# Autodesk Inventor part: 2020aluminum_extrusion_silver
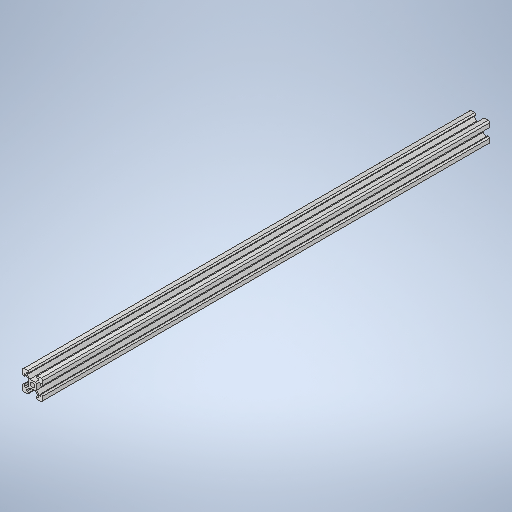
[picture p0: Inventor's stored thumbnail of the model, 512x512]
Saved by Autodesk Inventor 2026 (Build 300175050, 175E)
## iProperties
Created: 2021-10
Part Number: 2020aluminum_extrusion_silver
Material: Aluminum 6061
Document SubType Name: Modeling
Designer: casper
Density: 2.7 g/cm^3
Appearance: Satin - Silver
Author: casper
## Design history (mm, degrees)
sketch "Sketch1"
  geometry: L1 (-3.7, 2.639)-(-3.7, 0); L2 (-2.639, 3.7)-(-5.5, 6.561); L3 (-3.395, 8.2)-(-3.395, 10); L4 (-5.5, 8.2)-(-3.395, 8.2); L5 (-10, 3.395)-(-8.2, 3.395); L6 (0, 0)-(-10, 10); L7 (0, 3.7)-(-2.639, 3.7); L8 (-10, 10)-(-10, 3.395); L9 (-3.395, 10)-(-10, 10); L10 (-5.5, 6.561)-(-5.5, 8.2); L11 (-8.2, 3.395)-(-8.2, 5.5); L12 (-6.561, 5.5)-(-3.7, 2.639); L13 (-8.2, 5.5)-(-6.561, 5.5); L14 (-12.46, 0)-(4.76, 0) reference; L15 (-3.7, 0)-(0, 0); L16 (0, 0)-(0, 3.7); C1 r 2.3 at (0, 0); 3 further points
  constraints: 30 end point, 6 equal length, 6 perpendicular, 2 horizontal, 2 parallel, 2 vertical, 1 centre point, 1 coincident
  dimensions: "d0" = 1.5 distance between parallel lines of L2 L12; "d6" = 6.3 distance between parallel lines of L7 L9; "d9" = 4.6 diameter of C1; "d18" = 135 deg angle of L14 L6; "d22" = 20 diameter of L9 L15; "d34" = 11 diameter of L10 L16; "d35" = 6.79 diameter of L3 L16; "d36" = 1.8 distance between parallel lines of L9 L4
extrude "Extrusion1" new body sketch "Sketch1" stored distance "d24" = 440; taper "d25" = 0 deg
pattern_circular "Circular Pattern1" dims angle "d27" = 360 deg
chamfer "Chamfer1" distance "d37" = 1.185; stored, may be unused: second distance "d38" = 2, angle "d39" = 45 deg
fillet "Fillet1" dims "d40" = 1.5
body "Solid1"
